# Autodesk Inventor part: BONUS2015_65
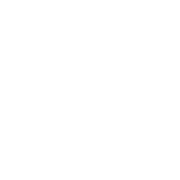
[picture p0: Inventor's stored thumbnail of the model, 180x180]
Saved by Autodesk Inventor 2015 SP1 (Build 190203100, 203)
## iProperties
Created: 2015-05
Part Number: BONUS2015_65
Material: Generisch
Document SubType Name: Modeling
Density: 1 g/cm^3
Appearance: Vorgabe
xx: 65
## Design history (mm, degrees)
